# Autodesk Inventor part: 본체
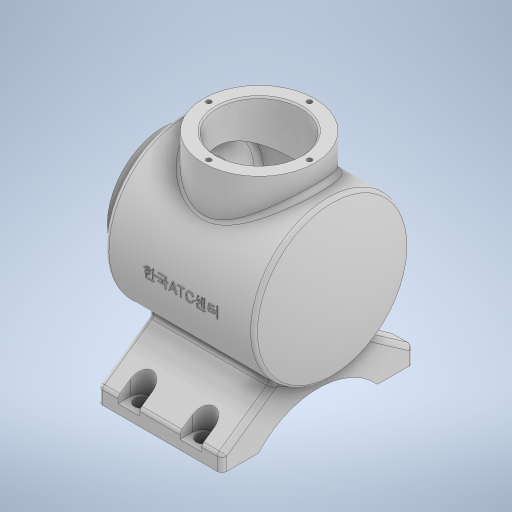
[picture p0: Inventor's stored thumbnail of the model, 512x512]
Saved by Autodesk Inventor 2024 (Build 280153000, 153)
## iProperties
Created: 2023-08
Part Number: 본체
Material: 일반
Document SubType Name: Modeling
Designer: Owner
Density: 1 g/cm^3
Appearance: 기본값
Author: Owner
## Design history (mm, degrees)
sketch "스케치1"
  geometry: L1 (0, 0)-(120, 0); L2 (0, 27)-(0, 36); L3 (0, 36)-(12, 36); L4 (12, 36)-(12, 50); L5 (12, 50)-(108.336, 50); L6 (0, 27)-(19, 27); L7 (19, 27)-(19, 43); L8 (19, 43)-(103.887, 43); A1 r 113 centre (7, 0) between (120, 0) and (108.336, 50); A2 r 106 centre (7, 0) between (113, 0) and (103.887, 43)
  constraints: 16 end point, 5 perpendicular, 4 point on circle, 2 centre point, 2 horizontal, 1 horizontal alignment, 1 point on line, 1 vertical, 1 vertical alignment
  dimensions: "d0" = 120 distance of L1.start L1.end; "d1" = 113 radius of A1; "d2" = 7 radial gap between concentric circles of A1 A2; "d3" = 108 distance from line of L4 L1.end; "d4" = 54 diameter of L6 L1; "d5" = 72 diameter of L3 L1; "d6" = 86 diameter of L8 L1; "d7" = 100 diameter of L5 L1; "d8" = 19 distance of L2.start L6.end
revolve "회전1" sketch "스케치1" stored, may be unused: angle "d9" = 90 deg
node "작업 평면2"
sketch "스케치3"
  geometry: L1 (42.278, -26.694)-(67, -62); L2 (67, -62)-(77, -62); L3 (77, -62)-(77, -38.5); L4 (77, 38.5)-(77, 62); L5 (77, 62)-(67, 62); L6 (67, 62)-(42.278, 26.694); A1 r 50 centre (0, 0) between (42.278, -26.694) and (42.278, 26.694) reference; A2 r 52.096 centre (112.096, 0) between (77, 38.5) and (77, -38.5); 2 further points
  constraints: 12 end point, 5 point on circle, 3 equal length, 2 vertical, 1 centre point, 1 horizontal, 1 horizontal alignment, 1 perpendicular, 1 vertical alignment
  dimensions: "d13" = 77 distance of L4.start L3.end; "d14" = 55 deg angle of L5 L6; "d15" = 10 distance of L4.end L5.end; "d16" = 17 distance from line of point (60, 0) L4; "d17" = 124 distance between parallel lines of L5 L2; "d18" = 77 distance from line of L4 point (0, 0)
extrude "돌출1" join sketch "스케치3" distance "d19" = 80; taper "d20" = 0 deg
node "작업 평면5"
sketch "스케치5"
  geometry: L1 (0, 0)-(80, 0) reference; L2 (67, 0)-(67, 8); L3 (53, 8)-(53, 0); L4 (80, 23.5)-(80, 0) reference; A1 r 7 centre (60, 8) between (67, 8) and (53, 8); 1 further point
  constraints: 4 end point, 2 point on circle, 2 point on line, 2 tangent, 1 centre point, 1 parallel, 1 vertical
  dimensions: "d26" = 14 distance of L3.end L2.start; "d27" = 8 distance from line of A1.centre L1; "d28" = 20 distance from line of A1.centre L4
extrude "돌출2" cut sketch "스케치5" distance "d29" = 33.75; taper "d30" = 0 deg
sketch "스케치6"
  geometry: L1 (53, -8)-(53, 0) reference; L2 (67, 0)-(67, -8) reference; L3 (53, 0)-(67, 0) reference; C1 r 4.5 at (60, -8); A1 r 7 centre (60, -8) between (53, -8) and (67, -8) reference; 1 further point
  constraints: 1 centre point, 1 coincident
  dimensions: "d31" = 9 diameter of C1
extrude "돌출3" cut sketch "스케치6" distance "d32" = 33.75; taper "d33" = 0 deg
node "작업 평면6"
node "작업 평면7"
sketch "스케치7"
  geometry: L1 (-20, -74.5)-(-20, -2.5) reference; C1 r 36 at (42, -38.5); 1 further point
  constraints: 1 centre point, 1 horizontal alignment
  dimensions: "d35" = 72 diameter of C1; "d36" = 62 distance from line of L1 C1.centre
extrude "돌출4" join sketch "스케치7" stored distance "d37" = 33.75; taper "d38" = 0 deg
sketch "스케치8"
  geometry: C1 r 27 at (0, 0); C2 r 36 at (0, 0) reference; 1 further point
  constraints: 1 centre point, 1 coincident, 1 horizontal alignment
  dimensions: "d39" = 54 diameter of C1
extrude "돌출5" cut sketch "스케치8" stored distance "d40" = 10; taper "d41" = 0 deg; dims "d13" = 77, "d14" = 55 deg, "d15" = 10, "d16" = 17, "d17" = 124, "d18" = 77
fillet "모깎기1" dims "d42" = 3
fillet "모깎기2" dims "d43" = 3
fillet "모깎기3" dims "d44" = 3
fillet "모깎기4" dims "d45" = 3
fillet "모깎기5" dims "d46" = 3
chamfer "모따기1" distance "d47" = 1; stored, may be unused: second distance "d48" = 2, angle "d49" = 45 deg
fillet "모깎기6" dims "d50" = 3
fillet "모깎기7" dims "d51" = 3
fillet "모깎기8" dims "d52" = 3
sketch "스케치9"
  geometry: 2 further points
  constraints: 1 vertical alignment
  dimensions: "d53" = 32.5 distance of point (0, 0) point (0, 32.5)
hole "구멍1" sketch "스케치9" at (0, 32.5) diameter "d54" = 3.242; stored, may be unused: countersink angle "d58" = 90 deg, drill point angle "d60" = 118 deg; dims "d55" = 8, "d56" = 4, "d57" = 2, "d59" = 10
sketch "스케치10"
  geometry: C1 r 36 at (0, 0) reference; C2 r 28 at (0, 0) reference; 2 further points
  constraints: 1 vertical alignment
  dimensions: "d64" = 32.5 distance of C1.centre point (0, 32.5)
hole "구멍2" sketch "스케치10" at (0, 32.5) diameter "d65" = 3.242; stored, may be unused: countersink angle "d69" = 90 deg, drill point angle "d71" = 118 deg; dims "d66" = 8, "d67" = 4, "d68" = 2, "d70" = 10
node "작업 평면8"
sketch "스케치11"
  geometry: 2 further points
  constraints: 1 horizontal alignment, 1 other
  dimensions: "d75" = 62 distance of point (-60.168, 0) point (1.832, 0)
feature "엠보싱1" sketch "스케치11" dims "d0" = 120, "d1" = 113, "d2" = 7, "d3" = 108, "d4" = 54, "d5" = 72, "d6" = 86, "d7" = 100, "d8" = 19, "d13" = 77, "d14" = 55 deg, "d15" = 10, "d16" = 17, "d17" = 124, "d18" = 77, "d76" = 0.5, "d77" = 0
feature "˂耀˄耀ˆ耀ˈ耀ˊ耀ˌ耀ˎ耀ː耀" dims "d0" = 120, "d1" = 113, "d2" = 7, "d3" = 108, "d4" = 54, "d5" = 72, "d6" = 86, "d7" = 100, "d8" = 19, "d9" = 90 deg, "d11" = 20, "d13" = 77, "d14" = 55 deg, "d15" = 10, "d16" = 17, "d17" = 124, "d18" = 77, "d19" = 80, "d20" = 0, "d25" = -6, "d26" = 14, "d27" = 8, "d28" = 20, "d29" = 33.75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
node "솔리드1"
mirror "미러1"
mirror "미러2"
pattern_circular "원형 패턴1" dims angle "d62" = 360 deg
pattern_circular "원형 패턴2" dims angle "d73" = 360 deg
node "투영된 루프1"
node "투영된 루프2"
node "투영된 루프3"
feature "A9D066F2-1C7D-4E18-AEED-F7BC21143FA4" dims "d54" = 3.242, "d55" = 8, "d56" = 4, "d57" = 2, "d58" = 90 deg, "d59" = 10, "d60" = 118 deg
